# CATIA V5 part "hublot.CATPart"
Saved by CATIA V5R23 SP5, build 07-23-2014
Part number: cache transparent
Definition: cache transparent
Source: made
Bounding box of the stored display mesh (mm): x -23 to -6, y -32 to 32, z -32 to 32
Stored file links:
  C:\wamp\www\COURS\CONCEPTION GMP1\TITRE 01-CATIA VOLUMIQUE\05--ACTIONNEUR DE VANNE\prof\CORRECTION\Assemblage\hublot.CATPart
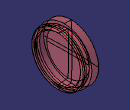
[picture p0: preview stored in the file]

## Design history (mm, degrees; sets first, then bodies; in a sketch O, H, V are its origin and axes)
Body1 "NONE" (main body)
  Solid1 "Manifold Solid #4539": solid without history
